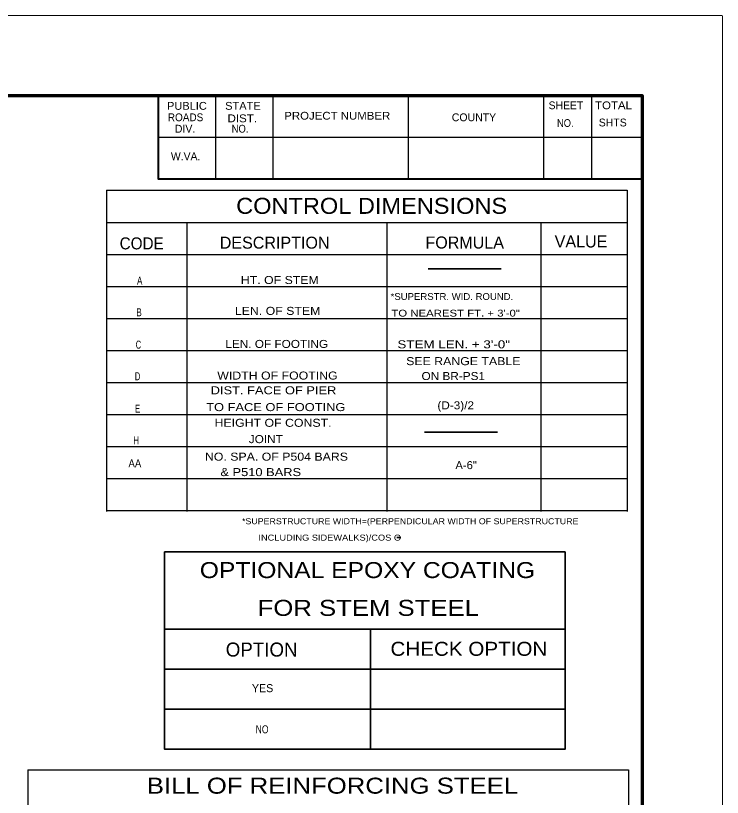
# Model space of a CAD drawing. Extents: x 14.14 to 17.34, y -1.61 to 0.38.
# Drawn here: x 16.604 to 17.339, y -0.432 to 0.382 of the extents above; entities that cross this region are included whole.
import ezdxf
from ezdxf.enums import TextEntityAlignment as Align

# ---------------------------------------------------------------- set-up
doc = ezdxf.new("R2010")
doc.units = 0
doc.header["$LTSCALE"] = 0.0033
doc.layers.add('1', color=7, linetype='Continuous', lineweight=40)

msp = doc.modelspace()

# ---------------------------------------------------------------- linework, layer by layer
at = {"layer": '1', "lineweight": 13}
for p, q in [((14.142583, 0.382), (17.339, 0.382)), ((17.33925, 0.381833), (17.33925, -1.604583))]:
    msp.add_line(p, q, dxfattribs=at)
at = {"layer": '1', "lineweight": 25}
for p, q in [((16.811833, 0.298667), (16.811833, 0.212)), ((16.871417, 0.298667), (16.871417, 0.212)), ((17.01225, 0.298667), (17.01225, 0.212)), ((17.153083, 0.298667), (17.153083, 0.212)), ((17.202917, 0.298667), (17.202917, 0.212)), ((16.75225, 0.255333), (17.256, 0.255333)), ((16.698417, 0.20025), (17.240083, 0.20025)), ((16.698417, 0.20025), (16.698417, -0.134167)), ((17.240083, 0.20025), (17.240083, -0.134167)), ((16.698417, 0.16675), (17.240083, 0.16675)), ((16.78175, 0.16675), (16.78175, -0.134167)), ((16.990083, 0.16675), (16.990083, -0.134167)), ((17.150417, 0.16675), (17.150417, -0.134167)), ((16.698417, 0.133417), (17.240083, 0.133417)), ((16.698417, 0.100083), (17.240083, 0.100083)), ((16.698417, 0.06675), (17.240083, 0.06675)), ((16.698417, 0.033417), (17.240083, 0.033417)), ((16.698417, 0.000083), (17.240083, 0.000083)), ((16.698417, -0.03325), (17.240083, -0.03325)), ((16.698417, -0.066583), (17.240083, -0.066583)), ((16.698417, -0.099917), (17.240083, -0.099917)), ((16.698417, -0.13325), (17.240083, -0.13325)), ((16.6165, -0.403167), (16.6165, -0.982417)), ((16.6165, -0.403167), (17.2415, -0.403167)), ((17.2415, -0.403167), (17.2415, -0.983833))]:
    msp.add_line(p, q, dxfattribs=at)
at = {"layer": '1', "lineweight": 35}
for p, q in [((17.033083, 0.118333), (17.109083, 0.118333)), ((17.029333, -0.051667), (17.105333, -0.051667)), ((17.0005, -0.16125), (17.004583, -0.16125)), ((16.758833, -0.25675), (17.1755, -0.25675)), ((16.973167, -0.382083), (16.973167, -0.257083)), ((16.758833, -0.298417), (17.1755, -0.298417)), ((16.758833, -0.340083), (17.1755, -0.340083))]:
    msp.add_line(p, q, dxfattribs=at)
at = {"layer": '1', "lineweight": 70}
msp.add_lwpolyline([(17.256, -1.521417), (17.256, 0.298667), (14.309333, 0.298667), (14.309333, -1.521417)], dxfattribs=at)
at = {"layer": '1'}
msp.add_lwpolyline([(16.75225, 0.298667), (16.75225, 0.212), (17.256, 0.212)], dxfattribs=at)
at = {"layer": '1', "lineweight": 35}
msp.add_lwpolyline([(16.758833, -0.176333), (17.1755, -0.176333), (17.1755, -0.38175), (16.758833, -0.38175)], close=True, dxfattribs=at)

# ---------------------------------------------------------------- texts
at = {"layer": '1'}
for s, height, width, p in [('PUBLIC', 0.008167, 1.05, (16.782, 0.284)), ('STATE', 0.008167, 1.05, (16.840292, 0.284)), ('TOTAL', 0.008084, 1.1, (17.225958, 0.284583)), ('ROADS', 0.008167, 0.95, (16.780583, 0.272083)), ('DIST.', 0.008167, 1.1, (16.839625, 0.271)), ('PROJECT NUMBER', 0.008084, 1.1, (16.938458, 0.27375)), ('NO.', 0.008084, 0.9, (17.175792, 0.266167)), ('NO.', 0.008167, 0.9, (16.837292, 0.260167)), ('HEIGHT OF CONST.', 0.008334, 1.15, (16.871667, -0.046)), ('JOINT', 0.008334, 1.1, (16.864125, -0.063)), ('AA', 0.008334, 0.9, (16.727833, -0.08825)), ('OPTIONAL EPOXY COATING', 0.01667, 1.15, (16.969875, -0.2035)), ('FOR STEM STEEL', 0.01667, 1.2, (16.97075, -0.242833)), ('NO', 0.008334, 0.8, (16.86025, -0.365083))]:
    msp.add_text(s, height=height, dxfattribs=dict(at, width=width)).set_placement(p, align=Align.CENTER)
for s, height, p in [('SHEET', 0.008084, (17.176458, 0.284583)), ('COUNTY', 0.008167, (17.08075, 0.272083)), ('SHTS', 0.008167, (17.225167, 0.266667)), ('DIV.', 0.008167, (16.780083, 0.260167)), ('W.VA.', 0.008084, (16.780667, 0.2315)), ('YES', 0.008334, (16.86075, -0.32225))]:
    msp.add_text(s, height=height, dxfattribs=at).set_placement(p, align=Align.CENTER)
for s, height, width, p in [('CONTROL DIMENSIONS', 0.01667, 1.1, (16.83325, 0.175667)), ('CODE', 0.0125, 0.95, (16.712, 0.138667)), ('A', 0.008334, 0.75, (16.730083, 0.102)), ('HT. OF STEM', 0.008334, 1.15, (16.838083, 0.102667)), ('*SUPERSTR. WID. ROUND. ', 0.007083, 1.05, (16.994, 0.086083)), ('B', 0.008334, 0.75, (16.729417, 0.069)), ('LEN. OF STEM', 0.008334, 1.15, (16.831917, 0.0705)), ('TO NEAREST FT. + 3\'-0"', 0.007083, 1.25, (16.99475, 0.06875)), ('C', 0.008334, 0.65, (16.728667, 0.035333)), ('LEN. OF FOOTING', 0.008334, 1.1, (16.822, 0.036083)), ('STEM LEN. + 3\'-0"', 0.008334, 1.25, (17.001083, 0.035667)), ('SEE RANGE TABLE', 0.008334, 1.15, (17.010167, 0.018167)), ('D', 0.008334, 0.65, (16.727833, 0.002417)), ('WIDTH OF FOOTING', 0.008334, 1.15, (16.813583, 0.003167)), ('ON BR-PS1', 0.008334, 1.1, (17.026167, 0.002667)), ('DIST. FACE OF PIER', 0.008334, 1.2, (16.80675, -0.012167)), ('E', 0.008334, 0.75, (16.727833, -0.03125)), ('TO FACE OF FOOTING', 0.008334, 1.2, (16.802083, -0.029667)), ('(D-3)/2', 0.008334, 1.1, (17.042667, -0.027833)), ('H', 0.008334, 0.65, (16.726333, -0.064167)), ('NO. SPA. OF P504 BARS', 0.008334, 1.15, (16.80075, -0.08125)), ('& P510 BARS', 0.008334, 1.2, (16.816833, -0.097333)), ('A-6"', 0.008334, 1.05, (17.061417, -0.090083)), ('*SUPERSTRUCTURE WIDTH=(PERPENDICULAR WIDTH OF SUPERSTRUCTURE', 0.00625, 1.1, (16.839333, -0.147417)), ('INCLUDING SIDEWALKS)/COS O', 0.00625, 1.15, (16.856417, -0.1645)), ('CHECK OPTION', 0.01458, 1.1, (16.993833, -0.284417)), ('BILL OF REINFORCING STEEL', 0.01667, 1.2, (16.74025, -0.427917))]:
    msp.add_text(s, height=height, dxfattribs=dict(at, width=width)).set_placement(p)
for s, height, p in [('DESCRIPTION ', 0.0125, (16.816167, 0.139417)), ('FORMULA', 0.0125, (17.03025, 0.139583)), ('VALUE', 0.0125, (17.16475, 0.140667)), ('OPTION', 0.01458, (16.822417, -0.285167))]:
    msp.add_text(s, height=height, dxfattribs=at).set_placement(p)

doc.saveas('drawing.dxf')
